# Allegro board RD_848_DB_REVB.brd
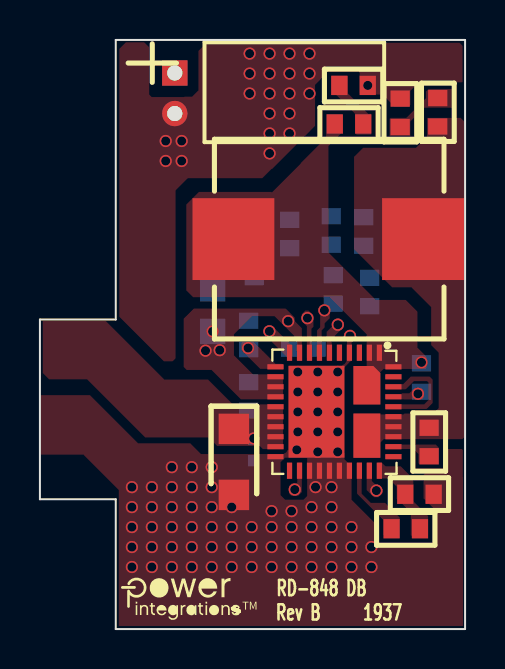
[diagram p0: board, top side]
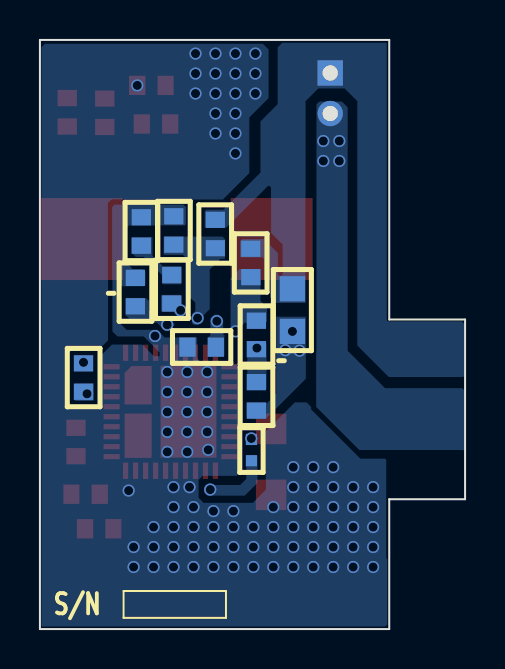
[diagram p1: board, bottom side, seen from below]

Outline 21.3 x 29.5 mm; copper layers: TOP, BOTTOM. Coordinates in mm from the lower left corner of the outline.
Outline path: 0,15.5 0,6.5 3.8,6.5 3.8,0 21.3,0 21.3,29.5 3.8,29.5 3.8,15.5 0,15.5

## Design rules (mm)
constraint set DEFAULT: min track width 0.508

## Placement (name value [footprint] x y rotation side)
C52  22 nF  [PISMC0603]  16.22 19.2 90 bottom
C53  100 nF  [PISMC0603]  19.12 11.88 90 bottom
C54  100 nF  [PISMC0603]  19.5 8.66 90 top
C56  22 nF  [PISMC0603]  10.45 14.02 90 bottom
C58  1 uF  [PISMC0603]  12.49 14.12 0 bottom
C60  270 uF  [PIPOLCAPCLYD200LS80030]  6.76 27.85 270 top
C61  1 uF  [PISMC0603]  19.73 6.75 180 top
C66  10 uF  [PISMC1206]  9.72 10.02 270 top
C69  470 pF  [PISMC0603]  18.05 25.14 90 top
C70  470 pF  [PISMC0603]  15 27.22 0 top
L3  6.8 uH  [PISMIND104CDMCCDS]  9.69 19.53 0 top
NOREF  -  []  3.77 2.72 0 top
NOREF#2  -  []  0 6.5 90 top
NOREF#3  -  []  -146.98 54.23 0 top
NOREF#4  -  []  0 6.5 0 top
NOREF#5  -  []  3.8 0 90 top
NOREF#6  -  []  21.3 0 90 top
NOREF#7  -  []  3.8 15.5 90 top
NOREF#8  -  []  -224.8 -144.78 0 top
NOREF#9  -  []  3.8 29.5 0 top
R59  41.2 k  [PISMR0603]  16.52 16.16 90 bottom
R60  10 k  [PISMR0603]  14.7 16.3 90 bottom
R62  100 k  [PISMR0603]  12.51 20.49 270 bottom
R63  30.9 k  [PISMR0603]  14.59 19.25 90 bottom
R64  0.01  [PISMR0805]  8.65 17.04 270 bottom
R65  2.00  [PISMR0603]  10.45 10.94 90 bottom
R66  2.00  [PISMR0603]  10.73 19.04 270 bottom
R68  200 k  [PISMR0402]  10.7 8.43 90 bottom
R70  100 k  [PISMR0603]  17.62 5.02 0 top
R71  2R  [PISMR0603]  19.93 25.17 90 top
R73  2R  [PISMR0603]  14.77 25.29 0 top
U4  SC8903QDHR  [PI_SM_40QFN_3EP]  14.76 10.88 270 top

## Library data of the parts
C52-C54 C56 C61 C69 C70 = CAP NP: room: Room3
C58 = CAP NP: alternate symbols: (pismc0603_1)
C60 = CAP POL
C66 = CAP NP: alternate symbols: (pismc1206_1)
L3 = INDUCTOR
R59 R60 R62 R63 R65 R66 R68 R70 R71 R73 = R
R64 = R: alternate symbols: (pismr0805_1)
U4 = SC8903QDHR_1

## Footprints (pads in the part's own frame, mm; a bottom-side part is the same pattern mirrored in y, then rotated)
PI_SM_40QFN_3EP
  rect 0.81x0.26 smd: 1(-2.955,2.25) 2(-2.955,1.75) 3(-2.955,1.25) 4(-2.955,0.75) 5(-2.955,0.25) 6(-2.955,-0.25) 7(-2.955,-0.75) 8(-2.955,-1.25) 9(-2.955,-1.75) 10(-2.955,-2.25) 21(2.955,-2.25) 22(2.955,-1.75) 23(2.955,-1.25) 24(2.955,-0.75) 25(2.955,-0.25) 26(2.955,0.25) 27(2.955,0.75) 28(2.955,1.25) 29(2.955,1.75) 30(2.955,2.25)
  rect 0.26x0.81 smd: 11(-2.25,-2.955) 12(-1.75,-2.955) 13(-1.25,-2.955) 14(-0.75,-2.955) 15(-0.25,-2.955) 16(0.25,-2.955) 17(0.75,-2.955) 18(1.25,-2.955) 19(1.75,-2.955) 20(2.25,-2.955) 31(2.25,2.955) 32(1.75,2.955) 33(1.25,2.955) 34(0.75,2.955) 35(0.25,2.955) 36(-0.25,2.955) 37(-0.75,2.955) 38(-1.25,2.955) 39(-1.75,2.955) 40(-2.25,2.955)
  custom 0.338x0.338 smd: 41(-1.325,1.625)
  rect 4.6x2.8 smd: 42(0,-0.9)
  rect 2.22x1.35 smd: 43(1.2,1.625)
PIPOLCAPCLYD200LS80030
  rect 1.27x1.27 hole 0.762: 1(0,0)
  round 1.27 hole 0.762: 2(2.032,0)
PISMC0603
  rect 0.813x0.965 smd: 1(0,0) 2(1.422,0)
PISMC1206
  rect 1.524x1.524 smd: 1(0,0) 2(3.302,0)
PISMIND104CDMCCDS
  rect 4.1x4.1 smd: 1(0,0) 2(9.5,0)
PISMR0402
  rect 0.559x0.559 smd: 1(0,0) 2(1.067,0)
PISMR0603
  rect 0.813x0.965 smd: 1(0,0) 2(1.422,0)
PISMR0805
  rect 1.27x1.27 smd: 1(0,0) 2(2.134,0)

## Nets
+5V BUS: C60.1 R62.1 R64.1 R66.1
GND: C52.2 C58.2 C60.2 C61.1 C66.2 C69.2 C70.2 R59.2 R63.2 U4.4 U4.20 U4.23 U4.24 U4.25 U4.26 U4.27 U4.29 U4.42
VDC-OUT: C66.1 R68.2 U4.15 U4.16 U4.17 U4.18 U4.19
N12933668: C54.2 L3.2 R71.1 U4.33 U4.34 U4.35 U4.43
N12935088: R62.2 R63.1 U4.8
N12935357: C54.1 U4.32
N12935384: C53.2 L3.1 R73.1 U4.1 U4.2 U4.40 U4.41
N12935833: C56.1 R65.2 U4.11
N12936316: C58.1 R64.2 R65.1 U4.9 U4.12 U4.13 U4.14
N12938228: C61.2 R70.2 U4.30
N12938960: R59.1 U4.6
N12939085: R60.1 U4.7
N12943061: R68.1 U4.22
N12947202: C53.1 U4.37
N12951187: R70.1 U4.28
N12952491: U4.36 U4.38
N12999713: C70.1 R73.2
N13000797: C52.1 R60.2
N13002188: C56.2 R66.2 U4.10
N129515020: C69.1 R71.2

Pads without a net: U4 3 5 21 31 39

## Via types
v1: diameter 0.61, hole 0.457, TOP to BOTTOM, 110 vias

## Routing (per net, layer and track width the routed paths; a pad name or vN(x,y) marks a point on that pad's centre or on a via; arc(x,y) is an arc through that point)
GND:
  vias: v1(4.61,7.11) v1(4.61,6.11) v1(4.61,5.11) v1(4.61,4.11) v1(4.61,3.11) v1(5.61,7.11) v1(5.61,6.11) v1(5.61,5.11) v1(5.61,4.11) v1(5.61,3.11) v1(6.3,24.44) v1(6.3,23.44) v1(6.61,8.11) v1(6.61,7.11) v1(6.61,6.11) v1(6.61,5.11) v1(6.61,4.11) v1(6.61,3.11) v1(7.1,24.44) v1(7.1,23.44) v1(7.61,8.11) v1(7.61,7.11) v1(7.61,6.11) v1(7.61,5.11) v1(7.61,4.11) v1(7.61,3.11) v1(8.61,8.11) v1(8.61,7.11) v1(8.61,6.11) v1(8.61,5.11) v1(8.61,4.11) v1(8.61,3.11) v1(9.61,6.11) v1(9.61,5.11) v1(9.61,4.11) v1(9.61,3.11) v1(10.51,28.82) v1(10.51,27.82) v1(10.51,26.82) v1(10.61,5.11) v1(10.61,4.11) v1(10.61,3.11) v1(11.51,28.82) v1(11.51,27.82) v1(11.51,26.82) v1(11.51,25.82) v1(11.51,24.82) v1(11.51,23.82) v1(11.61,5.91) v1(11.61,5.11) v1(11.61,4.11) v1(11.61,3.11) v1(12.51,28.82) v1(12.51,27.82) v1(12.51,26.82) v1(12.51,25.82) v1(12.51,24.82) v1(12.61,5.91) v1(12.61,5.11) v1(12.61,4.11) v1(12.61,3.11) v1(12.92,12.87) v1(12.92,11.87) v1(12.92,10.87) v1(12.92,9.87) v1(12.87,8.97) v1(13.51,28.82) v1(13.51,27.82) v1(13.51,26.82) v1(13.61,6.11) v1(13.61,5.11) v1(13.61,4.11) v1(13.61,3.11) v1(13.81,7.11) v1(13.92,12.87) v1(13.92,11.87) v1(13.92,10.87) v1(13.92,9.87) v1(13.92,8.87) v1(14.61,7.11) v1(14.61,6.11) v1(14.61,5.11) v1(14.61,4.11) v1(14.61,3.11) v1(14.92,12.87) v1(14.92,11.87) v1(14.92,10.87) v1(14.92,9.87) v1(14.92,8.87) v1(15.53,14.68) v1(15.61,5.11) v1(15.61,4.11) v1(15.61,3.11) v1(16.42,27.22) v1(16.61,4.11) v1(16.61,3.11) v1(16.86,6.93)
VDC-OUT:
  vias: v1(10.71,9.55)
N12935088:
  vias: v1(13.4,15.57)
N12935384:
  vias: v1(19.12,13.36)
N12935833:
  vias: v1(10.43,14.07)
N12936316:
  vias: v1(8.3,13.94) v1(8.65,14.9) v1(9.01,13.96) v1(12.44,15.42)
N12938960:
  vias: v1(14.93,15.24)
N12939085:
  vias: v1(14.25,15.96)
N12943061:
  vias: v1(12.77,6.99)
N12947202:
  vias: v1(18.94,11.78)
N13002188:
  vias: v1(11.5,14.91)

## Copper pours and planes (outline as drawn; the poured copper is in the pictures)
+5V BUS on BOTTOM: 0.04,15.29 0.17,15.41 3.87,15.41 3.93,15.47 3.93,29.33 3.95,29.36 9.16,29.36 9.39,29.13 9.39,26.28 10.25,25.42 10.25,22.85 12.11,21 12.97,21 13.05,20.92 13.05,20.11 11.95,20.11 9.87,22.19 9.79,22.19 9.72,22.12 9.72,19.84 9.13,19.25 9.13,17.75 9.21,17.68 9.31,17.68 9.39,17.75 9.39,18.84 10.07,19.53 11.17,19.53 11.27,19.43 11.27,18.64 11.24,18.61 10.15,18.61 9.77,18.23 9.77,16.61 9.49,16.33 7.99,16.33 7.99,26.44 7.36,27.07 6.04,27.07 5.4,26.44 5.4,14.2 3.83,12.62 0.09,12.62 0.04,12.67
GND on TOP: 4.91,9.3 7.53,9.3 7.53,9.3 8.07,8.76 9.45,8.76 9.46,8.76 12.21,8.76 12.56,9.11 12.69,9.11 12.74,9.06 12.74,8.68 12.64,8.58 12.28,8.58 12.05,8.36 12.05,6.71 12.28,6.48 13.2,6.48 13.39,6.66 13.39,7.5 13.38,7.5 13.38,8.34 13.39,8.34 13.39,9.08 13.48,9.17 14.87,9.17 15.26,8.79 15.26,8.5 15.43,8.33 15.61,8.33 15.61,6.48 16.8,5.28 16.8,4.41 17.03,4.19 19.68,4.19 19.83,4.34 19.83,5.94 19.22,6.55 19.22,7.72 19.32,7.82 20.01,7.82 20.23,8.05 20.23,8.89 20.36,9.02 21.14,9.02 21.19,8.97 21.19,7.63 21.2,7.61 21.2,0.15 3.95,0.15 3.95,6.96 2.17,8.74 0.04,8.74 -0.01,8.79 -0.01,11.68 0.02,11.71 2.51,11.71
GND on TOP: 16.37,8.33 16.63,8.33 16.63,7.42 16.8,7.24 16.93,7.24 17.19,6.99 17.19,6.83 16.96,6.6 16.73,6.6 16.37,6.96
GND on TOP: 15.48,15.01 15.61,15.01 15.81,14.8 15.81,14.55 15.61,14.35 15.61,13.53 15.61,13.53 15.61,13.46 15.23,13.08 15.23,12.65 15.15,12.57 14.72,12.57 14.7,12.6 14.7,13.18 15.12,13.18 15.38,13.44 15.38,14.42 15.26,14.55 15.26,14.78
GND on TOP: 3.98,15.64 3.98,29.05 4.31,29.38 5.22,29.38 5.48,29.13 5.48,26.77 5.6,26.64 7.23,26.64 7.24,26.65 7.62,26.65 7.94,26.97 7.94,28.95 8.35,29.36 21.02,29.36 21.17,29.2 21.17,27.4 21.15,27.38 18.99,27.38 18.56,26.94 18.56,26.26 18.46,26.16 17.77,26.16 17.16,26.77 16.09,26.77 16.02,26.84 16.02,27.86 15.81,28.06 14.57,28.06 14.09,27.58 14.09,27.55 13.78,27.25 13.78,25.19 11.64,23.05 11.61,23.05 11.14,22.58 7.41,22.58 6.8,21.97 6.8,13.56 6.64,13.41 6.21,13.41
GND on BOTTOM: 4.01,12.06 5.88,13.94 5.88,26.13 6.16,26.41 7.31,26.41 7.44,26.27 7.44,13.93 7.46,13.91 7.46,11.13 5.3,8.97 0.24,8.97 0.24,8.96 0.02,8.96 -0.01,8.99 -0.01,11.91 0.14,12.06
GND on BOTTOM: outline of 83 points within 3.9,0.13 21.22,29.31
VDC-OUT on TOP: 0.14,15.42 3.3,15.42 6.23,12.49 8.42,12.49 9.66,11.25 12.18,11.25 12.18,9.09 12.11,9.01 11.17,9.01 11.01,9.17 8.88,9.17 8.45,9.6 5.27,9.6 2.36,12.5 0.46,12.5 0.14,12.82
N12933668 on TOP: 19.4,25.6 21.08,25.6 21.25,25.43 21.25,9.6 21.15,9.5 21.14,9.51 17.23,9.51 17.01,9.29 16.84,9.29 16.83,9.3 15.97,9.3 15.76,9.5 15.76,10.46 16.04,10.74 18.21,10.74 18.25,10.79 19.7,10.79 19.98,11.07 19.98,13.84 19.6,14.22 19.6,16.12 18.61,17.11 17.64,17.11 15.74,19.02 15.74,23.65 16.19,24.1 18.84,24.1 19.4,24.66
N12935088 on TOP: 13.38,13.56 13.38,15.16 13.12,15.42 13.12,15.77 13.3,15.95 13.45,15.95 13.71,15.7 13.71,15.14 13.6,15.04 13.6,13.56 13.58,13.54 13.4,13.54
N12935088 on BOTTOM: 12.79,18 12.26,18.54 12.05,18.54 12.03,18.56 12.03,19.53 12.16,19.65 15.08,19.65 15.1,19.63 15.1,18.74 14.14,18.74 13.78,18.38 13.78,16.61 13.52,16.34 13.52,15.93 13.68,15.77 13.68,15.31 13.6,15.23 13.35,15.23 13.15,15.44 13.15,15.67 12.79,16.02
N12935357 on TOP: 19.82,9.24 19.98,9.09 19.98,8.22 19.04,8.22 18.96,8.3 18.96,8.76 18.7,9.02 17.39,9.02 17.39,9.24 19.82,9.24
N12935384 on TOP: 14.34,25.78 15.08,25.78 15.15,25.7 15.15,24.81 15.08,24.81 14.46,24.19 14.46,18.85 16.83,16.48 18.33,16.48 18.91,15.9 18.91,14.09 19.37,13.63 19.37,13.08 19.32,13.02 17.21,13.02 17.03,12.85 17.03,12.19 16.75,11.91 16.32,11.91 16.07,12.17 16.07,13.16 16.35,13.16 16.37,13.18 16.37,14.75 14.51,16.62 7.67,16.62 7.33,16.96 7.33,21.25 7.97,21.89 11.6,21.89 11.62,21.86 13.07,23.31 13.07,23.34 14.34,24.61
N12935833 on TOP: 11.8,13.28 12.11,13.28 12.13,13.26 12.16,13.26 12.18,13.23 12.18,13.06 12.16,13.03 11.03,13.03 10.1,13.96 10.1,14.33 10.15,14.38 10.71,14.38
N12935833 on BOTTOM: 10.91,14.33 10.91,12.09 10.81,11.99 10,11.99 9.95,12.04 9.95,14.3 10.02,14.38 10.86,14.38
N12936316 on TOP: 7.71,16.05 12.31,16.05 12.77,15.6 12.77,15.42 13.12,15.06 13.12,13.74 13.1,13.72 13.07,13.72 12.87,13.92 12.87,14.55 11.76,15.67 10.63,15.67 9.72,14.76 9.72,13.71 10.65,12.78 10.66,12.78 10.68,12.75 12.18,12.75 12.18,11.51 10.07,11.51 8.6,12.97 7.36,12.97 7.2,13.13 7.2,15.54
N12936316 on BOTTOM: 12.05,13.71 12.05,14.71 12.13,14.78 12.12,14.79 12.12,15.5 12.36,15.74 12.56,15.74 12.77,15.54 12.77,14.7 12.89,14.57 12.89,13.66 12.87,13.63 12.13,13.63
N12936316 on BOTTOM: 7.98,15.64 9.46,15.64 9.46,11.76 9.9,11.33 10.81,11.33 10.94,11.2 10.94,10.67 10.78,10.52 10,10.52 7.98,12.53
N12938228 on TOP: 17.11,8.33 17.11,8.33 17.13,8.33 17.31,8.15 18.07,8.15 18.71,7.51 18.71,6.4 19.45,5.66 19.45,4.67 18.61,4.67 18.58,4.69 18.58,5.84 17.9,6.52 17.87,6.52 17.87,7.13 17.46,7.54 16.88,7.54 16.88,8.3 16.88,8.33
N12938960 on TOP: 14.37,13.46 14.37,14.88 14.62,15.14 14.62,15.34 14.85,15.57 15,15.57 15.23,15.34 15.23,15.14 14.62,14.53 14.62,13.49 14.59,13.46
N12938960 on BOTTOM: 14.85,15.6 15.43,15.6 15.84,16 15.84,16.43 15.97,16.56 17.01,16.56 17.01,15.72 16.63,15.34 15.43,15.34 15.05,14.96 14.82,14.96 14.57,15.21 14.57,15.29 14.65,15.37 14.65,15.39
N12939085 on TOP: 13.88,14.96 14.04,15.11 14.04,15.78 14.05,15.78 13.96,15.87 13.96,16.07 14.11,16.23 14.47,16.23 14.52,16.17 14.52,15.56 14.26,15.31 14.26,15.11 14.11,14.96 14.11,13.48 14.09,13.46 13.88,13.46
N12939085 on BOTTOM: 13.93,15.9 13.93,16 14.21,16.28 14.21,16.68 14.26,16.73 15.18,16.73 15.23,16.68 15.23,15.9 14.63,15.9 14.4,15.67 14.16,15.67 14.11,15.72 14.11,15.72
N12943061 on TOP: 12.89,8.33 13.12,8.33 13.12,6.86 12.94,6.68 12.59,6.68 12.49,6.78 12.49,7.16 12.61,7.29 12.84,7.29 12.89,7.34
N12943061 on BOTTOM: 10.96,8.69 10.96,7.52 11.27,7.21 12.97,7.21 13.07,7.11 13.07,6.83 12.92,6.68 11.04,6.68 10.4,7.32 10.4,8.69
N12947202 on TOP: 18.51,11.81 18.76,12.06 19.12,12.06 19.22,11.96 19.22,11.58 19.14,11.5 18.25,11.5 18.25,11.5 18.13,11.5 18.1,11.53 17.34,11.53 17.31,11.56 17.31,11.73 18.07,11.73 18.15,11.81
N12951187 on TOP: 15.88,8.34 16.11,8.34 16.12,8.33 16.12,6.78 16.58,6.32 17.29,6.32 18.02,5.59 18.02,4.69 17.24,4.69 17.21,4.72 17.21,5.46 15.89,6.78 15.89,7.5 15.88,7.5
N12952491 on TOP: 18.58,12.64 19.52,12.64 19.67,12.49 19.67,11.32 19.38,11.02 17.36,11.02 17.35,11.04 17.35,11.25 19.25,11.25 19.47,11.48 19.47,12.34 19.4,12.42 18.74,12.42 18.33,12.01 17.31,12.01 17.31,12.26 18.2,12.26
N12999713 on TOP: 14.59,27.71 15.41,27.71 15.43,27.68 15.43,26.82 16.45,25.8 16.58,25.8 16.6,25.78 16.6,24.76 15.86,24.76 15.79,24.84 15.79,25.8 14.85,26.74 14.59,26.74
N13000797 on BOTTOM: 14.21,18.18 15.15,18.18 15.66,18.69 15.66,19.63 16.65,19.63 16.7,19.58 16.7,18.84 16.5,18.64 16.09,18.64 15.18,17.72 15.18,17.32 15.13,17.27 14.21,17.27
N13002188 on TOP: 12.61,13.61 12.61,14.2 11.67,15.14 11.29,15.14 11.22,15.06 11.22,14.78 12.41,13.59 12.59,13.59
N13002188 on BOTTOM: 10.4,18.03 11.29,18.03 11.75,17.57 11.75,14.86 11.57,14.68 11.42,14.68 11.24,14.86 11.24,15.14 11.04,15.34 9.97,15.34 9.92,15.39 9.92,16.1 10.25,16.43 10.25,17.88
N129515020 on TOP: 17.57,25.6 18.35,25.6 19.34,26.59 19.34,26.92 19.47,27.05 20.72,27.05 20.72,26.21 20.61,26.11 19.24,26.11 18.56,25.42 18.56,24.71 18.53,24.68 17.52,24.68 17.52,25.55

Small or netless copper shapes (teardrops, artwork), in the pictures only: 1 on BOTTOM

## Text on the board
Ref Des/Silkscreen Bottom: S/N
Ref Des/Silkscreen Top: Rev B | RD-848 DB | 1937
User.7: 13   MATERIAL FR4 COPPER 2oz THICKNESS 0.039"
User.9: FIGURE | FINISHED_SIZE | 18.0 | 30.0 | DRILL CHART: TOP to BOTTOM | ALL UNITS ARE IN MILS | TOLERANCE_DRILL | +3.0/-3.0 | PLATED | QTY | 110 | 2
